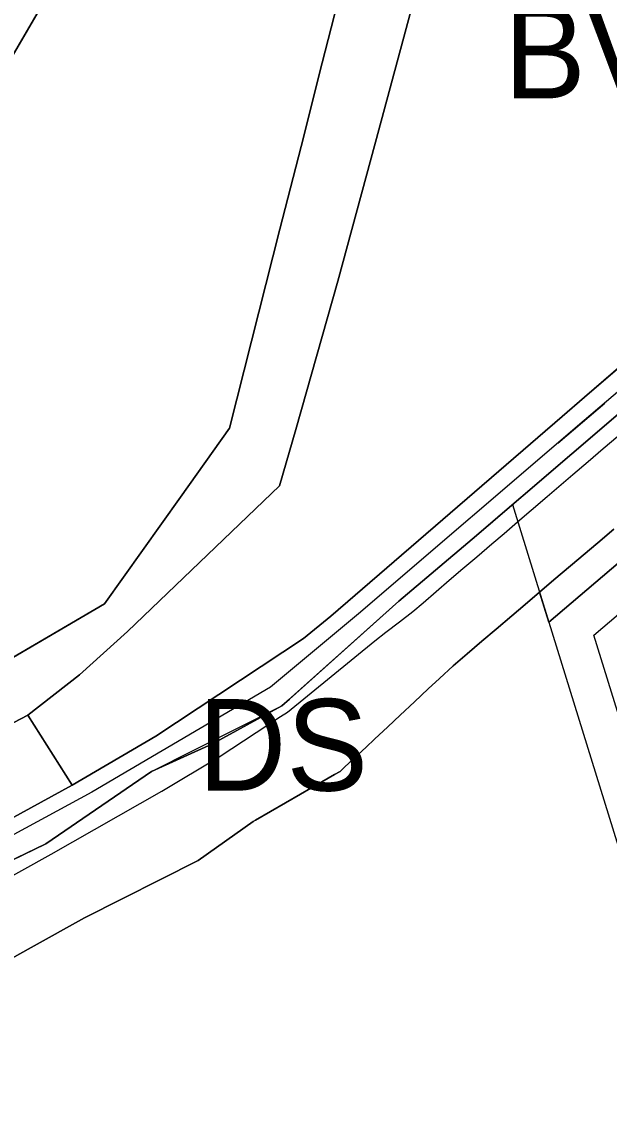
# Model space of a CAD drawing. Extents: x -555509 to -553005, y -1186756 to -1182560.
# Drawn here: x -554719.5 to -554629.7, y -1185487.3 to -1185321 of the extents above; entities that cross this region are included whole.
import ezdxf

# ---------------------------------------------------------------- set-up
doc = ezdxf.new("R2010")
doc.units = 0
for name, color, linetype in [('Level 15', 7, 'Continuous'), ('Level 31', 7, 'Continuous'), ('Level 36', 7, 'Continuous'), ('Level 52', 7, 'Continuous'), ('Level 59', 7, 'Continuous'), ('Level 6', 7, 'Continuous'), ('OBRYS_PLOCH', 7, 'Continuous'), ('rezerva_BV', 7, 'Continuous'), ('stav_AP', 7, 'Continuous'), ('stav_BV', 7, 'Continuous'), ('stav_DS', 7, 'Continuous'), ('stav_PU', 7, 'Continuous'), ('stav_WT', 7, 'Continuous'), ('stav_ZS', 7, 'Continuous'), ('stav_ZZ', 7, 'Continuous')]:
    doc.layers.add(name, color=color, linetype=linetype)

msp = doc.modelspace()

# ---------------------------------------------------------------- linework, layer by layer
at = {"layer": 'Level 15'}
for points in [[(-554680.05, -1185391.93), (-554677.6, -1185383.35), (-554671.14, -1185360.64), (-554665.38, -1185339.39), (-554660.73, -1185322.02), (-554657.69, -1185310.75), (-554654.76, -1185305.13), (-554646.4, -1185289.14), (-554639.48, -1185275.83), (-554632.63, -1185262.48), (-554627.88, -1185253.22), (-554621, -1185239.68)], [(-554670.31, -1185314.54), (-554673.54, -1185327.25), (-554676.78, -1185340.05), (-554680, -1185352.72), (-554683.21, -1185365.38), (-554687.71, -1185383.13)], [(-554687.71, -1185383.13), (-554695.2, -1185393.65)], [(-554710.64, -1185420.81), (-554703.3, -1185414.19), (-554680.05, -1185391.93)], [(-554695.2, -1185393.65), (-554706.82, -1185409.97)], [(-554706.82, -1185409.97), (-554734.36, -1185426.09)], [(-554783.65, -1185463.15), (-554779.51, -1185458.92), (-554718.55, -1185426.98), (-554710.64, -1185420.81)]]:
    msp.add_lwpolyline(points, dxfattribs=at)
at = {"layer": 'Level 31'}
for points in [[(-554445.49, -1185223.21), (-554454.96, -1185233.2), (-554483.05, -1185256.78), (-554490.83, -1185263.4), (-554522.76, -1185291.29), (-554542.15, -1185304.6), (-554577.54, -1185334.32), (-554633.5, -1185381.96), (-554668, -1185411.5), (-554681.46, -1185422.71), (-554708.78, -1185438.76), (-554758.85, -1185465.95), (-554795.57, -1185486.43), (-554821.6, -1185495.33), (-554849.36, -1185501.68)], [(-554637.55, -1185385.43), (-554630.36, -1185379.29)]]:
    msp.add_lwpolyline(points, dxfattribs=at)
at = {"layer": 'Level 36'}
msp.add_line((-554644.47, -1185394.78), (-554638.92, -1185412.79), dxfattribs=at)
for points in [[(-554760.96, -1185470.31), (-554743.55, -1185460.15), (-554715.8, -1185446.65), (-554699.63, -1185435.59), (-554679.72, -1185425.57), (-554661.85, -1185409.57), (-554647.54, -1185397.43), (-554646.64, -1185396.65), (-554644.47, -1185394.78)], [(-554638.92, -1185412.79), (-554627.18, -1185450.64), (-554622.56, -1185451.39)]]:
    msp.add_lwpolyline(points, dxfattribs=at)
at = {"layer": 'Level 52'}
for points in [[(-554715.19, -1185316.37), (-554721.98, -1185328.15), (-554728.42, -1185339.33), (-554731.79, -1185345.18), (-554734.88, -1185350.42), (-554742.18, -1185362.81), (-554744.55, -1185366.82), (-554747.05, -1185371.06), (-554752.81, -1185380.83), (-554760.45, -1185393.79), (-554768.14, -1185406.83), (-554772.69, -1185415.93), (-554786.97, -1185444.66), (-554790.07, -1185451.89), (-554783.65, -1185463.15), (-554777.58, -1185473.79), (-554773.94, -1185481.01), (-554750.17, -1185467.82), (-554741.93, -1185463.25), (-554714.96, -1185448.24), (-554698.05, -1185438.6)], [(-554698.05, -1185438.6), (-554689.29, -1185433.35), (-554679.91, -1185427.23), (-554678.86, -1185426.55), (-554665.52, -1185415.64), (-554663.8, -1185414.32), (-554661.71, -1185412.73), (-554659.7, -1185411.15), (-554658.14, -1185409.81), (-554656.13, -1185408.09), (-554654.12, -1185406.38), (-554652.03, -1185404.58), (-554649.92, -1185402.78), (-554647.63, -1185400.82), (-554645.75, -1185399.21), (-554643.68, -1185397.44), (-554641.63, -1185395.68), (-554639.15, -1185393.56), (-554635.22, -1185390.2), (-554632.91, -1185388.21), (-554630.58, -1185386.22), (-554628.38, -1185384.34)]]:
    msp.add_lwpolyline(points, dxfattribs=at)
at = {"layer": 'Level 6'}
for points in [[(-554715.19, -1185316.37), (-554721.98, -1185328.15), (-554728.42, -1185339.33), (-554731.79, -1185345.18), (-554734.88, -1185350.42), (-554742.18, -1185362.81), (-554744.55, -1185366.82), (-554747.05, -1185371.06), (-554752.81, -1185380.83), (-554760.45, -1185393.79), (-554768.14, -1185406.83), (-554772.69, -1185415.93), (-554786.97, -1185444.66), (-554790.07, -1185451.89), (-554783.65, -1185463.15), (-554777.58, -1185473.79), (-554773.94, -1185481.01), (-554750.17, -1185467.82), (-554741.93, -1185463.25), (-554714.96, -1185448.24), (-554698.05, -1185438.6)], [(-554698.05, -1185438.6), (-554689.29, -1185433.35), (-554679.91, -1185427.23), (-554678.86, -1185426.55), (-554665.52, -1185415.64), (-554663.8, -1185414.32), (-554661.71, -1185412.73), (-554659.7, -1185411.15), (-554658.14, -1185409.81), (-554656.13, -1185408.09), (-554654.12, -1185406.38), (-554652.03, -1185404.58), (-554649.92, -1185402.78), (-554647.63, -1185400.82), (-554645.75, -1185399.21), (-554643.68, -1185397.44), (-554641.63, -1185395.68), (-554639.15, -1185393.56), (-554635.22, -1185390.2), (-554632.91, -1185388.21), (-554630.58, -1185386.22), (-554628.38, -1185384.34)]]:
    msp.add_lwpolyline(points, dxfattribs=at)
at = {"layer": 'OBRYS_PLOCH'}
for p, q in [((-554531.78, -1185321.49), (-554638.92, -1185412.79)), ((-554633.44, -1185378.36), (-554618.68, -1185365.64)), ((-554636.89, -1185381.33), (-554633.44, -1185378.36)), ((-554631.43, -1185400.64), (-554628.99, -1185398.56)), ((-554635.58, -1185404.17), (-554631.43, -1185400.64)), ((-554638.13, -1185406.33), (-554635.58, -1185404.17)), ((-554640.34, -1185408.22), (-554638.13, -1185406.33)), ((-554642.53, -1185410.07), (-554640.34, -1185408.22)), ((-554640.34, -1185408.22), (-554642.53, -1185410.07)), ((-554640.33, -1185408.21), (-554640.34, -1185408.22)), ((-554638.92, -1185412.79), (-554640.33, -1185408.21)), ((-554646.95, -1185413.83), (-554649.16, -1185415.71)), ((-554649.16, -1185415.71), (-554651.4, -1185417.61)), ((-554651.4, -1185417.61), (-554653.52, -1185419.44)), ((-554655.63, -1185421.4), (-554653.52, -1185419.44)), ((-554653.52, -1185419.44), (-554655.63, -1185421.4)), ((-554710.64, -1185420.81), (-554718.55, -1185426.98)), ((-554655.63, -1185421.4), (-554657.34, -1185423)), ((-554657.34, -1185423), (-554659.44, -1185424.96)), ((-554659.44, -1185424.96), (-554661.63, -1185427.01)), ((-554718.55, -1185426.98), (-554711.78, -1185437.68)), ((-554711.78, -1185437.68), (-554698.96, -1185430.19)), ((-554690.31, -1185431.4), (-554699.63, -1185435.59)), ((-554666.84, -1185431.87), (-554668.11, -1185433.06)), ((-554666.84, -1185431.87), (-554665.57, -1185430.69)), ((-554665.57, -1185430.69), (-554666.84, -1185431.87)), ((-554668.11, -1185433.06), (-554670.16, -1185434.97)), ((-554670.16, -1185434.97), (-554670.82, -1185435.59)), ((-554699.63, -1185435.59), (-554715.8, -1185446.65)), ((-554673.6, -1185437.2), (-554675.27, -1185438.16)), ((-554673.6, -1185437.2), (-554671.68, -1185436.09)), ((-554671.68, -1185436.09), (-554673.6, -1185437.2)), ((-554670.82, -1185435.59), (-554671.68, -1185436.09)), ((-554675.27, -1185438.16), (-554676.89, -1185439.1)), ((-554683.72, -1185443.05), (-554676.89, -1185439.1)), ((-554676.89, -1185439.1), (-554683.72, -1185443.05)), ((-554684.1, -1185443.27), (-554692.49, -1185449.24)), ((-554684.1, -1185443.27), (-554683.72, -1185443.05)), ((-554683.72, -1185443.05), (-554684.1, -1185443.27)), ((-554715.8, -1185446.65), (-554743.55, -1185460.15)), ((-554692.49, -1185449.24), (-554709.87, -1185457.99)), ((-554709.87, -1185457.99), (-554718.03, -1185462.53)), ((-554718.03, -1185462.53), (-554736.83, -1185473))]:
    msp.add_line(p, q, dxfattribs=at)
for points in [[(-554588.35, -1185339.59), (-554594.02, -1185336.6), (-554595.16, -1185336), (-554581.44, -1185321.01), (-554582.54, -1185305.03), (-554583.52, -1185290.79), (-554585.87, -1185256.63), (-554586.41, -1185249.88), (-554586.6, -1185246.65), (-554587.16, -1185237.33), (-554607.25, -1185238.73), (-554621, -1185239.68), (-554627.88, -1185253.22), (-554632.63, -1185262.48), (-554639.48, -1185275.83), (-554646.4, -1185289.14), (-554654.76, -1185305.13), (-554657.69, -1185310.75), (-554660.73, -1185322.02), (-554665.38, -1185339.39), (-554671.14, -1185360.64), (-554677.6, -1185383.35), (-554680.05, -1185391.93)], [(-554694.99, -1185274.23), (-554703.22, -1185292.14), (-554708.82, -1185304.31), (-554711.08, -1185309.23), (-554715.19, -1185316.37), (-554721.98, -1185328.15), (-554728.42, -1185339.33), (-554731.79, -1185345.18), (-554734.88, -1185350.42), (-554742.18, -1185362.81), (-554744.55, -1185366.82), (-554747.05, -1185371.06), (-554752.81, -1185380.83), (-554760.45, -1185393.79), (-554768.14, -1185406.83), (-554772.69, -1185415.93)], [(-554761.09, -1185439.66), (-554755.74, -1185436.95), (-554734.36, -1185426.09), (-554706.82, -1185409.97), (-554695.2, -1185393.65), (-554687.71, -1185383.13), (-554683.21, -1185365.38), (-554680, -1185352.72), (-554676.78, -1185340.05), (-554673.54, -1185327.25), (-554670.31, -1185314.54), (-554667.06, -1185301.73), (-554660.25, -1185284.19)], [(-554588.35, -1185339.59), (-554602, -1185351.33), (-554618.68, -1185365.64), (-554633.44, -1185378.36), (-554636.89, -1185381.33), (-554672.25, -1185411.89), (-554676.42, -1185415.26), (-554698.96, -1185430.19)], [(-554690.31, -1185431.4), (-554679.72, -1185425.57), (-554678.56, -1185424.53), (-554661.85, -1185409.57), (-554650.64, -1185400.08), (-554620.16, -1185374.01)], [(-554620.16, -1185374.01), (-554650.64, -1185400.08), (-554661.85, -1185409.57)], [(-554698.96, -1185430.19), (-554676.42, -1185415.26), (-554672.25, -1185411.89), (-554636.89, -1185381.33)], [(-554680.05, -1185391.93), (-554703.3, -1185414.19), (-554710.64, -1185420.81)], [(-554661.85, -1185409.57), (-554678.56, -1185424.53), (-554679.72, -1185425.57), (-554690.31, -1185431.4)], [(-554653.52, -1185419.44), (-554651.4, -1185417.61), (-554649.16, -1185415.71), (-554646.95, -1185413.83), (-554644.55, -1185411.79), (-554642.53, -1185410.07)], [(-554642.53, -1185410.07), (-554644.55, -1185411.79), (-554646.95, -1185413.83)], [(-554665.57, -1185430.69), (-554663.52, -1185428.77), (-554661.63, -1185427.01), (-554659.44, -1185424.96), (-554657.34, -1185423), (-554655.63, -1185421.4)], [(-554711.78, -1185437.68), (-554718.55, -1185426.98), (-554779.51, -1185458.92), (-554783.65, -1185463.15), (-554777.58, -1185473.79), (-554711.78, -1185437.68)], [(-554661.63, -1185427.01), (-554663.52, -1185428.77), (-554665.57, -1185430.69)], [(-554698.96, -1185430.19), (-554711.78, -1185437.68), (-554777.58, -1185473.79)], [(-554715.8, -1185446.65), (-554699.63, -1185435.59), (-554690.31, -1185431.4)], [(-554671.68, -1185436.09), (-554670.82, -1185435.59), (-554670.16, -1185434.97), (-554668.11, -1185433.06), (-554666.84, -1185431.87)], [(-554676.89, -1185439.1), (-554675.27, -1185438.16), (-554673.6, -1185437.2)], [(-554795.98, -1185504.29), (-554788.44, -1185500.22), (-554769.17, -1185490.14), (-554736.83, -1185473), (-554718.03, -1185462.53), (-554709.87, -1185457.99), (-554692.49, -1185449.24), (-554684.1, -1185443.27)], [(-554775.16, -1185478.6), (-554743.55, -1185460.15), (-554715.8, -1185446.65)]]:
    msp.add_lwpolyline(points, dxfattribs=at)
at = {"layer": 'rezerva_BV'}
for p, q in [((-554721.98, -1185328.15), (-554715.19, -1185316.37)), ((-554721.98, -1185328.15), (-554715.19, -1185316.37)), ((-554531.78, -1185321.49), (-554638.92, -1185412.79)), ((-554531.78, -1185321.49), (-554638.92, -1185412.79))]:
    msp.add_line(p, q, dxfattribs=at)
for points in [[(-554622.99, -1185443.89), (-554632.02, -1185414.79), (-554532.23, -1185329.76), (-554513, -1185350.16), (-554622.99, -1185443.89)], [(-554638.92, -1185412.79), (-554627.18, -1185450.64), (-554622.56, -1185451.39)], [(-554638.92, -1185412.79), (-554627.18, -1185450.64), (-554622.56, -1185451.39)]]:
    msp.add_lwpolyline(points, dxfattribs=at)
at = {"layer": 'stav_AP'}
for p, q in [((-554531.78, -1185321.49), (-554638.92, -1185412.79)), ((-554640.34, -1185408.22), (-554642.53, -1185410.07)), ((-554640.33, -1185408.21), (-554640.34, -1185408.22)), ((-554638.92, -1185412.79), (-554640.33, -1185408.21)), ((-554642.53, -1185410.07), (-554644.55, -1185411.79)), ((-554649.16, -1185415.71), (-554651.4, -1185417.61)), ((-554651.4, -1185417.61), (-554653.52, -1185419.44)), ((-554653.52, -1185419.44), (-554655.63, -1185421.4)), ((-554655.63, -1185421.4), (-554657.34, -1185423)), ((-554657.34, -1185423), (-554659.44, -1185424.96)), ((-554659.44, -1185424.96), (-554661.63, -1185427.01)), ((-554661.63, -1185427.01), (-554663.52, -1185428.77)), ((-554663.52, -1185428.77), (-554665.57, -1185430.69)), ((-554666.84, -1185431.87), (-554668.11, -1185433.06)), ((-554665.57, -1185430.69), (-554666.84, -1185431.87)), ((-554668.11, -1185433.06), (-554670.16, -1185434.97)), ((-554670.16, -1185434.97), (-554670.82, -1185435.59)), ((-554673.6, -1185437.2), (-554675.27, -1185438.16)), ((-554671.68, -1185436.09), (-554673.6, -1185437.2)), ((-554670.82, -1185435.59), (-554671.68, -1185436.09)), ((-554675.27, -1185438.16), (-554676.89, -1185439.1)), ((-554676.89, -1185439.1), (-554683.72, -1185443.05)), ((-554684.1, -1185443.27), (-554692.49, -1185449.24)), ((-554683.72, -1185443.05), (-554684.1, -1185443.27)), ((-554692.49, -1185449.24), (-554709.87, -1185457.99))]:
    msp.add_line(p, q, dxfattribs=at)
for points in [[(-554644.55, -1185411.79), (-554646.95, -1185413.83), (-554649.16, -1185415.71)], [(-554709.87, -1185457.99), (-554718.03, -1185462.53), (-554736.83, -1185473), (-554769.17, -1185490.14), (-554788.44, -1185500.22)]]:
    msp.add_lwpolyline(points, dxfattribs=at)
at = {"layer": 'stav_BV'}
for p, q in [((-554633.44, -1185378.36), (-554618.68, -1185365.64)), ((-554636.89, -1185381.33), (-554633.44, -1185378.36)), ((-554710.64, -1185420.81), (-554718.55, -1185426.98)), ((-554718.55, -1185426.98), (-554711.78, -1185437.68)), ((-554711.78, -1185437.68), (-554698.96, -1185430.19))]:
    msp.add_line(p, q, dxfattribs=at)
for points in [[(-554588.35, -1185339.59), (-554594.02, -1185336.6), (-554595.16, -1185336), (-554581.44, -1185321.01), (-554582.54, -1185305.03), (-554583.52, -1185290.79), (-554585.87, -1185256.63), (-554586.41, -1185249.88), (-554586.6, -1185246.65), (-554587.16, -1185237.33), (-554607.25, -1185238.73), (-554621, -1185239.68), (-554627.88, -1185253.22), (-554632.63, -1185262.48), (-554639.48, -1185275.83), (-554646.4, -1185289.14), (-554654.76, -1185305.13), (-554657.69, -1185310.75), (-554660.73, -1185322.02), (-554665.38, -1185339.39), (-554671.14, -1185360.64), (-554677.6, -1185383.35), (-554680.05, -1185391.93)], [(-554694.99, -1185274.23), (-554703.22, -1185292.14), (-554708.82, -1185304.31), (-554711.08, -1185309.23), (-554715.19, -1185316.37), (-554721.98, -1185328.15), (-554728.42, -1185339.33), (-554731.79, -1185345.18), (-554734.88, -1185350.42), (-554742.18, -1185362.81), (-554744.55, -1185366.82), (-554747.05, -1185371.06), (-554752.81, -1185380.83), (-554760.45, -1185393.79), (-554768.14, -1185406.83), (-554772.69, -1185415.93)], [(-554761.09, -1185439.66), (-554755.74, -1185436.95), (-554734.36, -1185426.09), (-554706.82, -1185409.97), (-554695.2, -1185393.65), (-554687.71, -1185383.13), (-554683.21, -1185365.38), (-554680, -1185352.72), (-554676.78, -1185340.05), (-554673.54, -1185327.25), (-554670.31, -1185314.54), (-554667.06, -1185301.73), (-554660.25, -1185284.19)], [(-554698.96, -1185430.19), (-554676.42, -1185415.26), (-554672.25, -1185411.89), (-554636.89, -1185381.33)], [(-554680.05, -1185391.93), (-554703.3, -1185414.19), (-554710.64, -1185420.81)]]:
    msp.add_lwpolyline(points, dxfattribs=at)
at = {"layer": 'stav_DS'}
for p, q in [((-554620.16, -1185374.01), (-554650.64, -1185400.08)), ((-554631.43, -1185400.64), (-554628.99, -1185398.56)), ((-554650.64, -1185400.08), (-554661.85, -1185409.57)), ((-554635.58, -1185404.17), (-554631.43, -1185400.64)), ((-554638.13, -1185406.33), (-554635.58, -1185404.17)), ((-554661.85, -1185409.57), (-554678.56, -1185424.53)), ((-554649.16, -1185415.71), (-554646.95, -1185413.83)), ((-554651.4, -1185417.61), (-554649.16, -1185415.71)), ((-554653.52, -1185419.44), (-554651.4, -1185417.61)), ((-554655.63, -1185421.4), (-554653.52, -1185419.44)), ((-554657.34, -1185423), (-554655.63, -1185421.4)), ((-554679.72, -1185425.57), (-554690.31, -1185431.4)), ((-554678.56, -1185424.53), (-554679.72, -1185425.57)), ((-554663.52, -1185428.77), (-554661.63, -1185427.01)), ((-554665.57, -1185430.69), (-554663.52, -1185428.77)), ((-554690.31, -1185431.4), (-554699.63, -1185435.59)), ((-554668.11, -1185433.06), (-554666.84, -1185431.87)), ((-554666.84, -1185431.87), (-554665.57, -1185430.69)), ((-554670.16, -1185434.97), (-554668.11, -1185433.06)), ((-554670.82, -1185435.59), (-554670.16, -1185434.97)), ((-554699.63, -1185435.59), (-554715.8, -1185446.65)), ((-554676.89, -1185439.1), (-554675.27, -1185438.16)), ((-554683.72, -1185443.05), (-554676.89, -1185439.1)), ((-554692.49, -1185449.24), (-554684.1, -1185443.27)), ((-554684.1, -1185443.27), (-554683.72, -1185443.05)), ((-554715.8, -1185446.65), (-554743.55, -1185460.15)), ((-554709.87, -1185457.99), (-554692.49, -1185449.24)), ((-554718.03, -1185462.53), (-554709.87, -1185457.99))]:
    msp.add_line(p, q, dxfattribs=at)
for points in [[(-554642.53, -1185410.07), (-554640.34, -1185408.22), (-554638.13, -1185406.33)], [(-554646.95, -1185413.83), (-554644.55, -1185411.79), (-554642.53, -1185410.07)], [(-554661.63, -1185427.01), (-554659.44, -1185424.96), (-554657.34, -1185423)], [(-554675.27, -1185438.16), (-554673.6, -1185437.2), (-554671.68, -1185436.09), (-554670.82, -1185435.59)], [(-554769.17, -1185490.14), (-554736.83, -1185473), (-554718.03, -1185462.53)]]:
    msp.add_lwpolyline(points, dxfattribs=at)
at = {"layer": 'stav_PU'}
for p, q in [((-554638.92, -1185412.79), (-554531.78, -1185321.49)), ((-554687.71, -1185383.13), (-554695.2, -1185393.65)), ((-554695.2, -1185393.65), (-554706.82, -1185409.97)), ((-554628.99, -1185398.56), (-554631.43, -1185400.64)), ((-554631.43, -1185400.64), (-554635.58, -1185404.17)), ((-554635.58, -1185404.17), (-554638.13, -1185406.33)), ((-554638.13, -1185406.33), (-554640.33, -1185408.21)), ((-554640.33, -1185408.21), (-554638.92, -1185412.79)), ((-554706.82, -1185409.97), (-554734.36, -1185426.09)), ((-554690.31, -1185431.4), (-554699.63, -1185435.59)), ((-554699.63, -1185435.59), (-554715.8, -1185446.65)), ((-554715.8, -1185446.65), (-554743.55, -1185460.15))]:
    msp.add_line(p, q, dxfattribs=at)
for points in [[(-554680.05, -1185391.93), (-554677.6, -1185383.35), (-554671.14, -1185360.64), (-554665.38, -1185339.39), (-554660.73, -1185322.02), (-554657.69, -1185310.75), (-554654.76, -1185305.13), (-554646.4, -1185289.14), (-554639.48, -1185275.83), (-554632.63, -1185262.48), (-554627.88, -1185253.22), (-554621, -1185239.68)], [(-554670.31, -1185314.54), (-554673.54, -1185327.25), (-554676.78, -1185340.05), (-554680, -1185352.72), (-554683.21, -1185365.38), (-554687.71, -1185383.13)], [(-554620.16, -1185374.01), (-554650.64, -1185400.08), (-554661.85, -1185409.57)], [(-554698.05, -1185438.6), (-554689.29, -1185433.35), (-554679.91, -1185427.23), (-554678.86, -1185426.55), (-554665.52, -1185415.64), (-554663.8, -1185414.32), (-554661.71, -1185412.73), (-554659.7, -1185411.15), (-554658.14, -1185409.81), (-554656.13, -1185408.09), (-554654.12, -1185406.38), (-554652.03, -1185404.58), (-554649.92, -1185402.78), (-554647.63, -1185400.82), (-554645.75, -1185399.21), (-554643.68, -1185397.44), (-554641.63, -1185395.68), (-554639.15, -1185393.56), (-554635.22, -1185390.2), (-554632.91, -1185388.21), (-554630.58, -1185386.22), (-554628.38, -1185384.34)], [(-554710.64, -1185420.81), (-554703.3, -1185414.19), (-554680.05, -1185391.93)], [(-554661.85, -1185409.57), (-554678.56, -1185424.53), (-554679.72, -1185425.57), (-554690.31, -1185431.4)], [(-554783.65, -1185463.15), (-554779.51, -1185458.92), (-554718.55, -1185426.98), (-554710.64, -1185420.81)], [(-554773.94, -1185481.01), (-554750.17, -1185467.82), (-554741.93, -1185463.25), (-554714.96, -1185448.24), (-554698.05, -1185438.6)]]:
    msp.add_lwpolyline(points, dxfattribs=at)
at = {"layer": 'stav_WT'}
for points in [[(-554588.35, -1185339.59), (-554602, -1185351.33), (-554618.68, -1185365.64), (-554633.44, -1185378.36), (-554636.89, -1185381.33), (-554672.25, -1185411.89), (-554676.42, -1185415.26), (-554698.96, -1185430.19)], [(-554690.31, -1185431.4), (-554679.72, -1185425.57), (-554678.56, -1185424.53), (-554661.85, -1185409.57), (-554650.64, -1185400.08), (-554620.16, -1185374.01)], [(-554698.96, -1185430.19), (-554711.78, -1185437.68), (-554777.58, -1185473.79)], [(-554715.8, -1185446.65), (-554699.63, -1185435.59), (-554690.31, -1185431.4)], [(-554775.16, -1185478.6), (-554743.55, -1185460.15), (-554715.8, -1185446.65)]]:
    msp.add_lwpolyline(points, dxfattribs=at)
at = {"layer": 'stav_ZS'}
msp.add_lwpolyline([(-554711.78, -1185437.68), (-554718.55, -1185426.98), (-554779.51, -1185458.92), (-554783.65, -1185463.15), (-554777.58, -1185473.79), (-554711.78, -1185437.68)], dxfattribs=at)
at = {"layer": 'stav_ZZ'}
msp.add_lwpolyline([(-554731.79, -1185345.18), (-554728.42, -1185339.33), (-554721.98, -1185328.15), (-554715.19, -1185316.37)], dxfattribs=at)

# ---------------------------------------------------------------- texts
at = {"layer": 'Level 59'}
for s, p in [('BV', (-554645.75, -1185332.7)), ('DS', (-554692.54, -1185438.54))]:
    msp.add_text(s, height=14, dxfattribs=at).set_placement(p)

doc.saveas('drawing.dxf')
